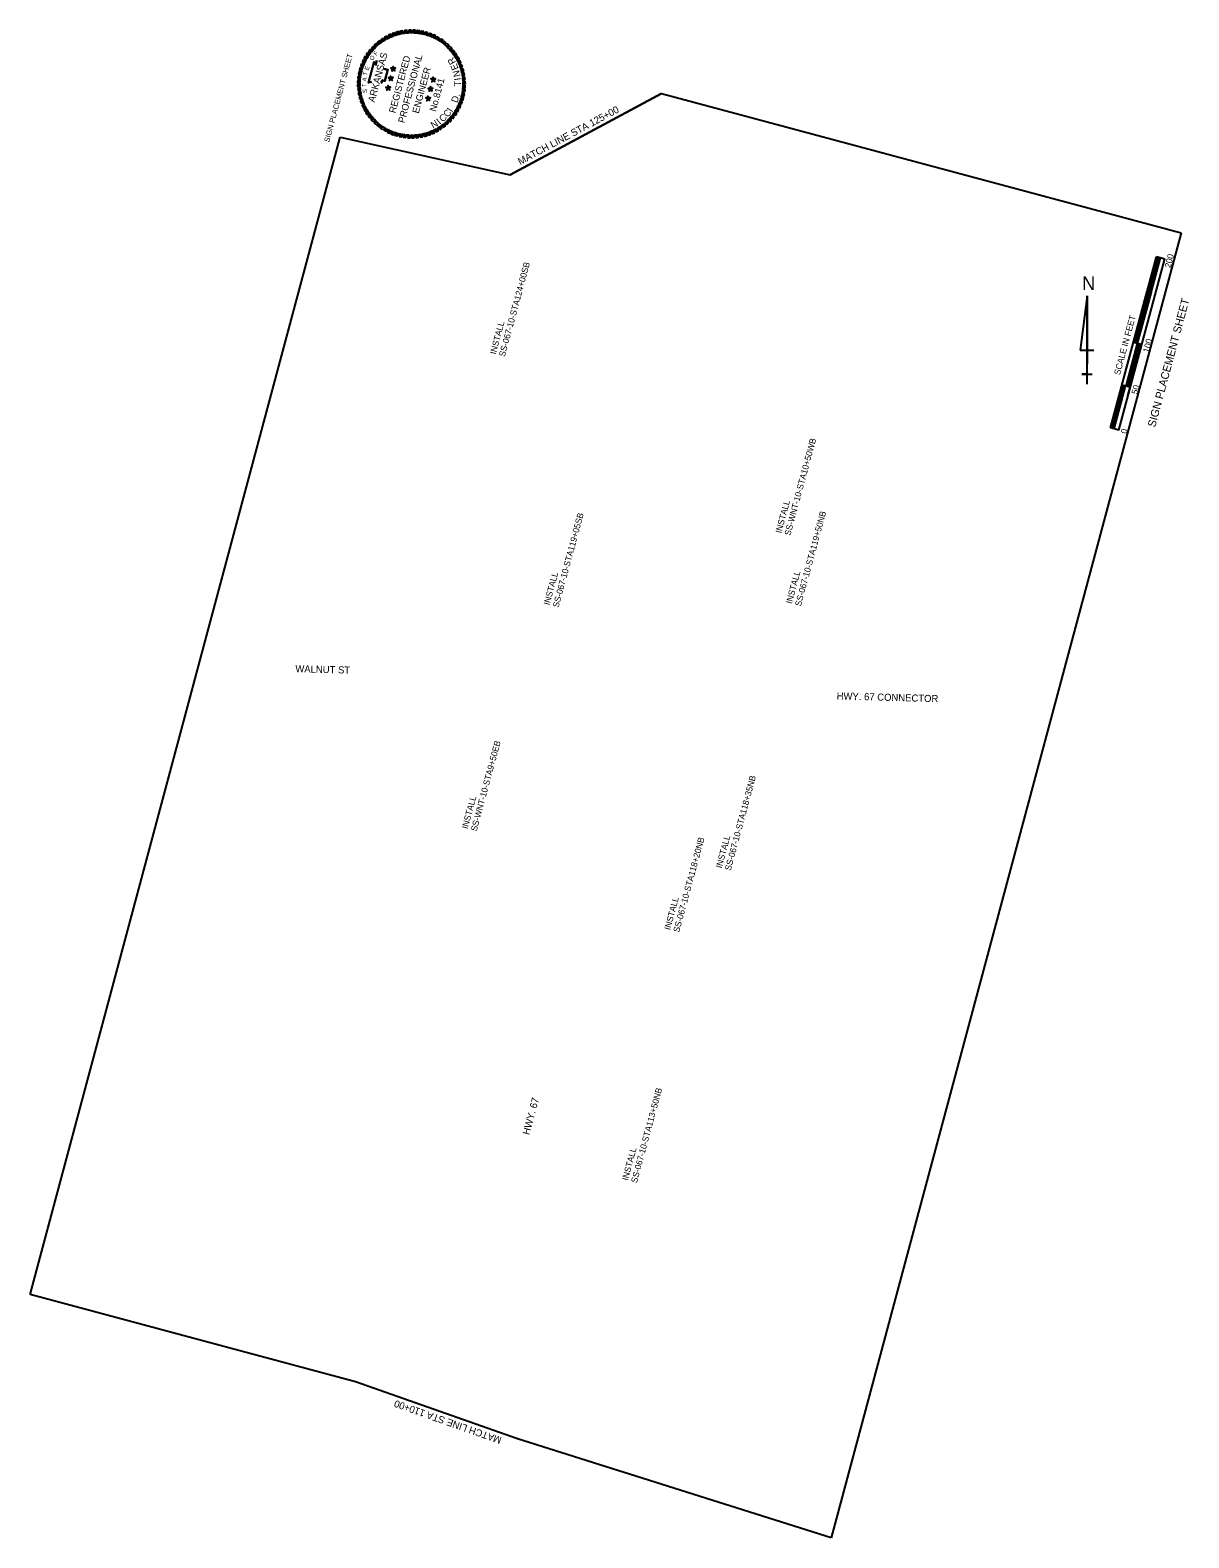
# Model space of a CAD drawing. Extents: x 992047 to 993355, y 1839705 to 1841407.
import ezdxf

# ---------------------------------------------------------------- set-up
doc = ezdxf.new("R2010")
doc.units = 0
for name, color, linetype in [('5', 7, 'Continuous'), ('63', 7, 'Continuous'), ('G-ANNO-SYMB', 7, 'Continuous'), ('G-ANNO-TEXT', 7, 'Continuous'), ('Level 10', 7, 'Continuous'), ('Plan Notes', 7, 'Continuous'), ('R_Annotation', 7, 'Continuous'), ('R_No Plot', 7, 'Continuous')]:
    doc.layers.add(name, color=color, linetype=linetype)

msp = doc.modelspace()

# ---------------------------------------------------------------- linework, layer by layer
at = {"layer": '5'}
for p, q in [((992759.9, 1841335.3), (992589, 1841243.7)), ((992597.4, 1839816.5), (992414.5, 1839881))]:
    msp.add_line(p, q, dxfattribs=at)
at = {"layer": '63'}
for p, q in [((993240.2, 1841107.1), (993232.5, 1841045.5)), ((993240.2, 1841007.1), (993240.2, 1841107.1)), ((993240.2, 1841107.1), (993240.2, 1841030.1)), ((993232.5, 1841045.5), (993247.9, 1841045.5)), ((993240.2, 1841018.6), (993234.4, 1841018.6)), ((993234.4, 1841018.6), (993246, 1841018.6)), ((993240.2, 1841007.1), (993240.2, 1841030.1)), ((993240.2, 1841007.1), (993240.2, 1841018.6))]:
    msp.add_line(p, q, dxfattribs=at)
at = {"layer": 'G-ANNO-SYMB'}
for points in [[(992472.6, 1841406.7), (992470, 1841406.4), (992466.8, 1841403.1), (992469.6, 1841403.6)], [(992477.4, 1841406.9), (992474.8, 1841406.8), (992471.3, 1841403.8), (992474.1, 1841404)], [(992482.2, 1841406.7), (992479.6, 1841406.9), (992475.8, 1841404.1), (992478.7, 1841404.1)], [(992438, 1841392.2), (992436, 1841390.5), (992435.3, 1841385.9), (992437.3, 1841387.9)], [(992441.7, 1841395.2), (992439.6, 1841393.6), (992438.6, 1841389.1), (992440.7, 1841390.9)], [(992445.7, 1841397.9), (992443.5, 1841396.4), (992442.1, 1841392), (992444.4, 1841393.7)], [(992449.8, 1841400.2), (992447.5, 1841399), (992445.8, 1841394.6), (992448.2, 1841396.1)], [(992454.2, 1841402.2), (992451.8, 1841401.1), (992449.7, 1841397), (992452.2, 1841398.3)], [(992458.6, 1841403.9), (992456.2, 1841403), (992453.8, 1841399), (992456.4, 1841400.1)], [(992463.2, 1841405.2), (992460.7, 1841404.5), (992458, 1841400.7), (992460.7, 1841401.6)], [(992467.9, 1841406.1), (992465.3, 1841405.6), (992462.3, 1841402.1), (992465.1, 1841402.8)], [(992486.9, 1841406.2), (992484.3, 1841406.5), (992480.4, 1841404), (992483.2, 1841403.8)], [(992491.6, 1841405.2), (992489.1, 1841405.8), (992484.9, 1841403.6), (992487.7, 1841403.2)], [(992496.2, 1841404), (992493.7, 1841404.7), (992489.4, 1841402.9), (992492.2, 1841402.2)], [(992500.7, 1841402.3), (992498.3, 1841403.3), (992493.8, 1841401.8), (992496.5, 1841400.9)], [(992505, 1841400.3), (992502.7, 1841401.5), (992498.2, 1841400.3), (992500.8, 1841399.3)], [(992509.2, 1841398), (992506.9, 1841399.3), (992502.3, 1841398.6), (992504.9, 1841397.3)], [(992513.2, 1841395.4), (992511, 1841396.9), (992506.4, 1841396.4), (992508.8, 1841395)], [(992516.9, 1841392.4), (992514.9, 1841394.1), (992510.2, 1841394), (992512.5, 1841392.4)], [(992520.4, 1841389.2), (992518.6, 1841391), (992513.9, 1841391.3), (992516.1, 1841389.5)], [(992423.3, 1841373.6), (992422.2, 1841371.2), (992423.3, 1841366.7), (992424.4, 1841369.3)], [(992425.7, 1841377.7), (992424.3, 1841375.5), (992425.1, 1841370.9), (992426.4, 1841373.4)], [(992428.3, 1841381.7), (992426.8, 1841379.6), (992427.2, 1841374.9), (992428.7, 1841377.3)], [(992431.2, 1841385.5), (992429.6, 1841383.4), (992429.6, 1841378.8), (992431.3, 1841381.1)], [(992434.5, 1841389), (992432.7, 1841387.1), (992432.3, 1841382.4), (992434.2, 1841384.6)], [(992523.7, 1841385.7), (992521.9, 1841387.6), (992517.3, 1841388.3), (992519.3, 1841386.3)], [(992526.7, 1841381.9), (992525.1, 1841384), (992520.5, 1841385.1), (992522.4, 1841382.9)], [(992529.3, 1841378), (992527.9, 1841380.2), (992523.5, 1841381.6), (992525.1, 1841379.3)], [(992531.7, 1841373.8), (992530.4, 1841376.1), (992526.1, 1841377.9), (992527.6, 1841375.5)], [(992533.7, 1841369.5), (992532.6, 1841371.9), (992528.4, 1841374), (992529.7, 1841371.5)], [(992418.4, 1841360.1), (992417.9, 1841357.6), (992420, 1841353.5), (992420.4, 1841356.3)], [(992419.7, 1841364.7), (992419, 1841362.2), (992420.8, 1841358), (992421.4, 1841360.7)], [(992421.3, 1841369.2), (992420.4, 1841366.8), (992421.9, 1841362.4), (992422.7, 1841365.1)], [(992457.1, 1841363.1), (992456.4, 1841363.9), (992454.4, 1841363.8), (992456.1, 1841362.7)], [(992457.1, 1841363.1), (992456.1, 1841362.7), (992455.5, 1841360.8), (992457.1, 1841362)], [(992457.1, 1841363.1), (992457.6, 1841364), (992456.9, 1841365.9), (992456.4, 1841363.9)], [(992457.1, 1841363.1), (992458.1, 1841362.8), (992459.7, 1841364.1), (992457.6, 1841364)], [(992457.1, 1841363.1), (992457.1, 1841362), (992458.8, 1841360.9), (992458.1, 1841362.8)], [(992535.3, 1841365), (992534.5, 1841367.5), (992530.5, 1841369.9), (992531.6, 1841367.3)], [(992536.6, 1841360.4), (992536, 1841363), (992532.2, 1841365.7), (992533.1, 1841363)], [(992537.6, 1841355.8), (992537.1, 1841358.3), (992533.5, 1841361.3), (992534.2, 1841358.6)], [(992538.2, 1841351), (992537.9, 1841353.6), (992534.6, 1841356.9), (992535, 1841354.1)], [(992416.9, 1841350.7), (992416.8, 1841348.1), (992419.6, 1841344.4), (992419.6, 1841347.2)], [(992416.8, 1841346), (992416.8, 1841343.3), (992419.9, 1841339.8), (992419.7, 1841342.6)], [(992417, 1841341.2), (992417.2, 1841338.6), (992420.6, 1841335.3), (992420.1, 1841338.1)], [(992417.5, 1841355.5), (992417.1, 1841352.9), (992419.6, 1841348.9), (992419.8, 1841351.7)], [(992451.3, 1841341.6), (992450.6, 1841342.5), (992448.6, 1841342.3), (992450.3, 1841341.2)], [(992451.3, 1841341.6), (992450.3, 1841341.2), (992449.8, 1841339.3), (992451.4, 1841340.6)], [(992451.3, 1841341.6), (992451.9, 1841342.5), (992451.2, 1841344.4), (992450.6, 1841342.5)], [(992451.3, 1841341.6), (992452.3, 1841341.4), (992453.9, 1841342.6), (992451.9, 1841342.5)], [(992451.3, 1841341.6), (992451.4, 1841340.6), (992453.1, 1841339.5), (992452.3, 1841341.4)], [(992454.2, 1841352.4), (992453.5, 1841353.2), (992451.5, 1841353.1), (992453.2, 1841352)], [(992454.2, 1841352.4), (992453.2, 1841352), (992452.7, 1841350), (992454.2, 1841351.3)], [(992454.2, 1841352.4), (992454.8, 1841353.3), (992454, 1841355.1), (992453.5, 1841353.2)], [(992454.2, 1841352.4), (992455.2, 1841352.1), (992456.8, 1841353.4), (992454.8, 1841353.3)], [(992454.2, 1841352.4), (992454.2, 1841351.3), (992455.9, 1841350.2), (992455.2, 1841352.1)], [(992499.1, 1841340.3), (992498.5, 1841341.1), (992496.5, 1841341), (992498.2, 1841339.9)], [(992499.1, 1841340.3), (992498.2, 1841339.9), (992497.6, 1841338), (992499.2, 1841339.3)], [(992499.1, 1841340.3), (992499.7, 1841341.2), (992499, 1841343.1), (992498.5, 1841341.1)], [(992499.1, 1841340.3), (992500.2, 1841340), (992501.7, 1841341.3), (992499.7, 1841341.2)], [(992499.1, 1841340.3), (992499.2, 1841339.3), (992500.9, 1841338.2), (992500.2, 1841340)], [(992502, 1841351.1), (992501.4, 1841351.9), (992499.3, 1841351.8), (992501, 1841350.7)], [(992502, 1841351.1), (992501, 1841350.7), (992500.5, 1841348.7), (992502.1, 1841350)], [(992502, 1841351.1), (992502.6, 1841351.9), (992501.9, 1841353.8), (992501.4, 1841351.9)], [(992502, 1841351.1), (992503, 1841350.8), (992504.6, 1841352), (992502.6, 1841351.9)], [(992502, 1841351.1), (992502.1, 1841350), (992503.8, 1841348.9), (992503, 1841350.8)], [(992536.7, 1841332), (992537.3, 1841334.6), (992535.1, 1841338.7), (992534.7, 1841335.9)], [(992538.4, 1841346.2), (992538.3, 1841348.9), (992535.2, 1841352.4), (992535.5, 1841349.6)], [(992537.6, 1841336.7), (992538, 1841339.3), (992535.5, 1841343.3), (992535.3, 1841340.5)], [(992538.2, 1841341.5), (992538.3, 1841344.1), (992535.5, 1841347.8), (992535.6, 1841345)], [(992417.5, 1841336.4), (992418, 1841333.9), (992421.6, 1841330.9), (992420.9, 1841333.6)], [(992418.5, 1841331.8), (992419.2, 1841329.2), (992422.9, 1841326.5), (992422.1, 1841329.2)], [(992419.8, 1841327.2), (992420.7, 1841324.7), (992424.7, 1841322.3), (992423.6, 1841324.9)], [(992421.5, 1841322.7), (992422.5, 1841320.3), (992426.7, 1841318.2), (992425.4, 1841320.7)], [(992496.3, 1841329.6), (992495.6, 1841330.4), (992493.6, 1841330.3), (992495.3, 1841329.2)], [(992496.3, 1841329.6), (992495.3, 1841329.2), (992494.8, 1841327.2), (992496.3, 1841328.5)], [(992496.3, 1841329.6), (992496.8, 1841330.5), (992496.1, 1841332.4), (992495.6, 1841330.4)], [(992496.3, 1841329.6), (992497.3, 1841329.3), (992498.9, 1841330.6), (992496.8, 1841330.5)], [(992496.3, 1841329.6), (992496.3, 1841328.5), (992498, 1841327.4), (992497.3, 1841329.3)], [(992531.8, 1841318.6), (992532.9, 1841321), (992531.8, 1841325.5), (992530.7, 1841322.9)], [(992533.8, 1841323), (992534.7, 1841325.4), (992533.2, 1841329.8), (992532.4, 1841327.1)], [(992535.4, 1841327.5), (992536.2, 1841330), (992534.4, 1841334.2), (992533.7, 1841331.5)], [(992423.5, 1841318.4), (992424.7, 1841316.1), (992429, 1841314.3), (992427.5, 1841316.7)], [(992425.8, 1841314.2), (992427.2, 1841312), (992431.7, 1841310.6), (992430, 1841312.9)], [(992428.5, 1841310.2), (992430.1, 1841308.2), (992434.6, 1841307.1), (992432.7, 1841309.3)], [(992431.4, 1841306.5), (992433.2, 1841304.6), (992437.8, 1841303.9), (992435.8, 1841305.9)], [(992517.2, 1841300), (992519.1, 1841301.7), (992519.8, 1841306.3), (992517.8, 1841304.3)], [(992520.7, 1841303.2), (992522.5, 1841305.1), (992522.8, 1841309.8), (992521, 1841307.6)], [(992523.9, 1841306.7), (992525.5, 1841308.8), (992525.5, 1841313.4), (992523.8, 1841311.1)], [(992526.8, 1841310.5), (992528.3, 1841312.6), (992527.9, 1841317.3), (992526.4, 1841314.9)], [(992529.5, 1841314.5), (992530.8, 1841316.7), (992530, 1841321.3), (992528.7, 1841318.8)], [(992434.7, 1841303), (992436.6, 1841301.2), (992441.2, 1841300.9), (992439.1, 1841302.7)], [(992438.2, 1841299.8), (992440.2, 1841298.1), (992444.9, 1841298.2), (992442.6, 1841299.8)], [(992441.9, 1841296.8), (992444.1, 1841295.3), (992448.7, 1841295.8), (992446.3, 1841297.2)], [(992445.9, 1841294.2), (992448.2, 1841292.9), (992452.8, 1841293.6), (992450.3, 1841294.9)], [(992450.1, 1841291.9), (992452.5, 1841290.7), (992457, 1841291.9), (992454.4, 1841292.9)], [(992454.4, 1841289.9), (992456.9, 1841288.9), (992461.3, 1841290.4), (992458.6, 1841291.3)], [(992458.9, 1841288.2), (992461.4, 1841287.5), (992465.7, 1841289.3), (992463, 1841290)], [(992463.5, 1841287), (992466.1, 1841286.4), (992470.2, 1841288.6), (992467.4, 1841289)], [(992468.2, 1841286), (992470.8, 1841285.7), (992474.7, 1841288.2), (992471.9, 1841288.4)], [(992472.9, 1841285.5), (992475.5, 1841285.3), (992479.3, 1841288.1), (992476.5, 1841288.1)], [(992477.7, 1841285.3), (992480.3, 1841285.4), (992483.8, 1841288.4), (992481, 1841288.2)], [(992482.5, 1841285.5), (992485.1, 1841285.8), (992488.3, 1841289.1), (992485.6, 1841288.6)], [(992487.2, 1841286.1), (992489.8, 1841286.5), (992492.8, 1841290.1), (992490, 1841289.4)], [(992491.9, 1841287), (992494.4, 1841287.7), (992497.1, 1841291.5), (992494.4, 1841290.6)], [(992496.5, 1841288.3), (992499, 1841289.2), (992501.4, 1841293.2), (992498.8, 1841292.1)], [(992501, 1841290), (992503.4, 1841291), (992505.4, 1841295.2), (992502.9, 1841293.9)], [(992505.3, 1841292), (992507.6, 1841293.2), (992509.3, 1841297.6), (992506.9, 1841296.1)], [(992509.5, 1841294.3), (992511.6, 1841295.8), (992513, 1841300.2), (992510.8, 1841298.5)], [(992513.4, 1841297), (992515.5, 1841298.6), (992516.5, 1841303.1), (992514.4, 1841301.3)]]:
    msp.add_lwpolyline(points, close=True, dxfattribs=at)
for points in [[(992432.4, 1841348.1), (992429.1, 1841347.5), (992435.4, 1841371.2), (992437.4, 1841368.6), (992437.8, 1841370.2), (992438.1, 1841371.5), (992438.6, 1841372.8)], [(992432.4, 1841348.5), (992429.6, 1841348), (992435.6, 1841370.3), (992437.6, 1841367.7), (992438.2, 1841370.1), (992438.5, 1841371.4), (992439, 1841372.7)], [(992447, 1841363.9), (992447.2, 1841363.3), (992447.8, 1841362.9), (992449.1, 1841362.4), (992450.4, 1841362.1), (992447, 1841349.6), (992445.2, 1841350.1), (992444.4, 1841350.3), (992443.9, 1841349.5), (992443.5, 1841347.8), (992443.1, 1841347.7)], [(992447.3, 1841364), (992447.5, 1841363.5), (992448, 1841363.3), (992449.2, 1841362.8), (992450.8, 1841362.4), (992447.3, 1841349.2), (992445.1, 1841349.7), (992444.6, 1841349.9), (992444.3, 1841349.4), (992443.8, 1841347.5), (992443.2, 1841347.3)]]:
    msp.add_lwpolyline(points, dxfattribs=at)
at = {"layer": 'Level 10'}
for p, q in [((993276.1, 1840955.4), (993327.9, 1841148.6)), ((993287.5, 1841035.1), (993318.6, 1841151)), ((993293.5, 1841054.2), (993319.4, 1841150.8)), ((993294.2, 1841054), (993320.1, 1841150.6)), ((993295, 1841053.8), (993320.9, 1841150.4)), ((993295.8, 1841053.6), (993321.7, 1841150.2)), ((993296.6, 1841053.4), (993322.4, 1841150)), ((993297.3, 1841053.2), (993323.2, 1841149.8)), ((993327.9, 1841148.5), (993318.6, 1841151)), ((993266.8, 1840957.9), (993308.2, 1841112.4)), ((993297.3, 1841053.2), (993312.9, 1841111.2)), ((993284.4, 1841004.9), (993297.3, 1841053.2)), ((993285.2, 1841004.7), (993298.1, 1841053)), ((993285.9, 1841004.5), (993298.9, 1841052.8)), ((993286.7, 1841004.3), (993299.7, 1841052.6)), ((993287.5, 1841004.1), (993300.4, 1841052.4)), ((993288.3, 1841003.9), (993301.2, 1841052.2)), ((993302, 1841052), (993292.7, 1841054.4)), ((993286.4, 1840994), (993296.8, 1841032.6)), ((993267.6, 1840957.6), (993280.5, 1841005.9)), ((993268.4, 1840957.4), (993281.3, 1841005.7)), ((993269.1, 1840957.2), (993282.1, 1841005.5)), ((993269.9, 1840957), (993282.9, 1841005.3)), ((993270.7, 1840956.8), (993283.6, 1841005.1)), ((993289, 1841003.7), (993279.8, 1841006.1)), ((993266.8, 1840957.9), (993277.2, 1840996.5)), ((993276.1, 1840955.4), (993266.8, 1840957.9))]:
    msp.add_line(p, q, dxfattribs=at)
at = {"layer": 'R_No Plot'}
for p, q in [((992589, 1841243.7), (992759.9, 1841335.3)), ((992759.9, 1841335.3), (993346.3, 1841178.2)), ((992047.1, 1839979.5), (992397.2, 1841286.2)), ((992397.2, 1841286.2), (992589, 1841243.7)), ((993346.3, 1841178.2), (992951.5, 1839704.8)), ((992414.5, 1839881), (992047.1, 1839979.5)), ((992597.4, 1839816.5), (992414.5, 1839881)), ((992951.5, 1839704.8), (992597.4, 1839816.5))]:
    msp.add_line(p, q, dxfattribs=at)

# ---------------------------------------------------------------- texts
at = {"layer": '63'}
msp.add_text('N', height=15.4, rotation=360, dxfattribs=at).set_placement((993234.6, 1841113.5))
at = {"layer": 'G-ANNO-SYMB'}
for s, height, rotation, p in [('ARKANSAS', 7.89, 75, (992435.9, 1841324.9)), ('O', 4.84, 56.2218, (992433.6, 1841372.1)), ('F', 4.84, 50.3628, (992437.8, 1841377.7)), ('REGISTERED', 7.64, 75, (992459.3, 1841312.7)), ('PROFESSIONAL', 7.642, 75, (992469.6, 1841301.5)), ('R', 7.64, 120.478, (992528, 1841370.7)), ('T', 4.84, 76.4789, (992427.2, 1841355.2)), ('E', 4.84, 71.672, (992429, 1841361.1)), ('ENGINEER', 7.64, 75, (992485.7, 1841312.3)), ('E', 7.64, 112.6498, (992530.9, 1841363.6)), ('N', 7.64, 103.7033, (992532.9, 1841355.1)), ('T', 4.84, 91.9015, (992426.5, 1841342.8)), ('A', 4.84, 83.6788, (992426.5, 1841348.9)), ('S', 4.84, 94.7726, (992427.6, 1841336.2)), ('No.8141', 7.61, 75, (992505.1, 1841314.4)), ('I', 7.64, 99.2301, (992533.5, 1841350.8)), ('T', 7.64, 91.7747, (992533.6, 1841343.5)), ('D', 7.64, 71.6451, (992529.3, 1841324.3)), ('.', 7.64, 79.846, (992531.9, 1841331.9)), ('N', 7.64, 30.2676, (992502, 1841295.6)), ('I', 7.64, 39.2141, (992509.5, 1841300)), ('C', 7.64, 43.6873, (992513, 1841302.6)), ('C', 7.64, 51.5155, (992518.6, 1841307.9)), ('I', 7.64, 59.3437, (992523.5, 1841313.8))]:
    msp.add_text(s, height=height, rotation=rotation, dxfattribs=at).set_placement(p)
at = {"layer": 'G-ANNO-TEXT'}
for height, p in [(6, (992384.6, 1841279.8)), (9, (993317.1, 1840958))]:
    msp.add_text('SIGN PLACEMENT SHEET', height=height, rotation=75, dxfattribs=at).set_placement(p)
at = {"layer": 'Level 10'}
for s, height, p in [('200', 7, (993334.4, 1841138)), ('SCALE IN FEET', 7.001, (993277.3, 1841017.1)), ('100', 7, (993309.9, 1841042.3)), ('50', 7, (993296.9, 1840995.2)), ('0', 7, (993284.8, 1840950.7))]:
    msp.add_text(s, height=height, rotation=75.0003, dxfattribs=at).set_placement(p)
at = {"layer": 'Plan Notes'}
for s, rotation, p in [('MATCH LINE STA 125+00', 28.1934, (992600.3, 1841254.5)), ('WALNUT ST', 358.4354, (992346.4, 1840682.1)), ('HWY. 67 CONNECTOR', 358.4525, (992957.5, 1840651.3)), ('HWY. 67', 74.9354, (992610.5, 1840159.2)), ('MATCH LINE STA 110+00', 160.5626, (992580, 1839818.2))]:
    msp.add_text(s, height=8, rotation=rotation, dxfattribs=at).set_placement(p)
at = {"layer": 'R_Annotation'}
for s, p in [('SS-067-10-STA124+00SB', (992582.9, 1841037.7)), ('INSTALL', (992572.8, 1841040.4)), ('SS-WNT-10-STA10+50WB', (992905.2, 1840835.8)), ('INSTALL', (992895.1, 1840838.5)), ('SS-067-10-STA119+50NB', (992917.1, 1840756)), ('SS-067-10-STA119+05SB', (992643.6, 1840754.6)), ('INSTALL', (992633.4, 1840757.3)), ('INSTALL', (992906.9, 1840758.8)), ('SS-WNT-10-STA9+50EB', (992551.1, 1840501.9)), ('SS-067-10-STA118+35NB', (992837.9, 1840457.6)), ('INSTALL', (992541, 1840504.6)), ('SS-067-10-STA118+20NB', (992779.7, 1840387.8)), ('INSTALL', (992827.8, 1840460.3)), ('INSTALL', (992769.6, 1840390.5)), ('SS-067-10-STA113+50NB', (992732, 1840105)), ('INSTALL', (992721.9, 1840107.7))]:
    msp.add_text(s, height=7, rotation=75, dxfattribs=at).set_placement(p)

doc.saveas('drawing.dxf')
